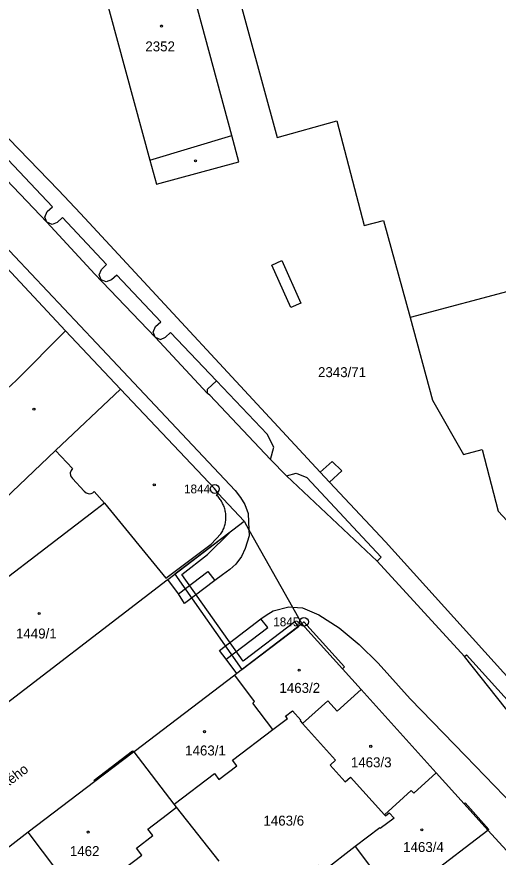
# Model space of a CAD drawing. Extents: x -821458 to -820266, y -1071458 to -1069826.
# Drawn here: x -821268.4 to -821186.2, y -1070550.7 to -1070407.2 of the extents above; entities that cross this region are included whole.
import ezdxf

# ---------------------------------------------------------------- set-up
doc = ezdxf.new("R2010")
doc.units = 0
for name, color, linetype in [('Vrstva 1', 7, 'Continuous'), ('Vrstva 13', 7, 'Continuous'), ('Vrstva 2', 7, 'Continuous'), ('Vrstva 4', 7, 'Continuous'), ('Vrstva 5', 7, 'Continuous'), ('Vrstva 7', 7, 'Continuous'), ('Vrstva 8', 7, 'Continuous')]:
    doc.layers.add(name, color=color, linetype=linetype)

msp = doc.modelspace()

# ---------------------------------------------------------------- linework, layer by layer
at = {"layer": 'Vrstva 1'}
for p, q in [((-821260.09, -1070460.79), (-821280.98, -1070438.5)), ((-821136.87, -1070441.33), (-821201.26, -1070458.54)), ((-821231.22, -1070519.61), (-821248.4, -1070532.7)), ((-821196.79, -1070536.31), (-821209.6, -1070522.1)), ((-821241.57, -1070541.65), (-821248.4, -1070532.7)), ((-821203.9, -1070558.21), (-821187.96, -1070546.11)), ((-821182.72, -1070551.87), (-821187.96, -1070546.11))]:
    msp.add_line(p, q, dxfattribs=at)
for points in [[(-821258.7, -1070367.71), (-821252.21, -1070365.96), (-821249.43, -1070365.21), (-821241.65, -1070362.96), (-821223.96, -1070427.77), (-821213.75, -1070424.96), (-821209.09, -1070442.84), (-821205.81, -1070441.98), (-821201.26, -1070458.54)], [(-821231.73, -1070427.45), (-821242.6, -1070387.17), (-821256.75, -1070390.96), (-821245.69, -1070431.69), (-821244.58, -1070435.78), (-821230.52, -1070431.97), (-821231.73, -1070427.45)], [(-821183.73, -1070520.92), (-821205.46, -1070496.83), (-821215, -1070486.68), (-821216.61, -1070484.97), (-821257.56, -1070440.79), (-821261.33, -1070436.77), (-821285.11, -1070412.22)], [(-821201.26, -1070458.54), (-821197.43, -1070472.66), (-821192.14, -1070481.93), (-821188.95, -1070481.1), (-821186.21, -1070491.62), (-821180.01, -1070498.29), (-821178.27, -1070497.75), (-821177.4, -1070501.1), (-821167.28, -1070512), (-821150.8, -1070507.61), (-821150.3, -1070509.44), (-821144.52, -1070507.96), (-821149.15, -1070489.84), (-821125.19, -1070483.48), (-821136.87, -1070441.33)], [(-821260.09, -1070460.79), (-821268.54, -1070469.28), (-821271.57, -1070472.02), (-821273.93, -1070474.15)], [(-821229.6, -1070493.33), (-821234.05, -1070488.58), (-821234.63, -1070487.82), (-821250.74, -1070470.77), (-821260.09, -1070460.79)], [(-821270.46, -1070489.5), (-821261.8, -1070481.24), (-821258.92, -1070484.33), (-821259.17, -1070484.65), (-821259.3, -1070485.04), (-821259.24, -1070485.58), (-821258.94, -1070486.03), (-821256.92, -1070488.18), (-821256.56, -1070488.5), (-821256.1, -1070488.63), (-821255.75, -1070488.6), (-821255.43, -1070488.46), (-821255.24, -1070488.28), (-821253.43, -1070490.23), (-821254.92, -1070491.37), (-821280.12, -1070510.63)], [(-821274.99, -1070528.04), (-821242.73, -1070503.37), (-821242.62, -1070503.28), (-821229.6, -1070493.33)], [(-821229.6, -1070493.33), (-821228.78, -1070494.79), (-821221.34, -1070508), (-821219.73, -1070510.86)], [(-821219.73, -1070510.86), (-821230.84, -1070519.32), (-821231.22, -1070519.61)], [(-821209.6, -1070522.1), (-821212.82, -1070518.52), (-821219.73, -1070510.86)], [(-821224.7, -1070528.92), (-821228.12, -1070524.38), (-821227.82, -1070524.15), (-821231.22, -1070519.61)], [(-821219.62, -1070527.87), (-821215.31, -1070524), (-821213.7, -1070525.78), (-821209.6, -1070522.1)], [(-821224.7, -1070528.92), (-821222.21, -1070527.03), (-821222.52, -1070526.64), (-821221.34, -1070525.7), (-821219.92, -1070527.32), (-821220.03, -1070527.42), (-821219.62, -1070527.87)], [(-821219.62, -1070527.87), (-821214, -1070534.15), (-821214.91, -1070535), (-821212.36, -1070537.82), (-821211.43, -1070537.02), (-821205.64, -1070543.47)], [(-821241.57, -1070541.65), (-821234.65, -1070536.44), (-821233.9, -1070537.43), (-821230.84, -1070535.14), (-821231.6, -1070534.16), (-821224.7, -1070528.92)], [(-821248.4, -1070532.7), (-821248.5, -1070532.78), (-821255.09, -1070537.77), (-821266.51, -1070546.45)], [(-821205.64, -1070543.47), (-821201.07, -1070539.3), (-821200.61, -1070539.8), (-821196.79, -1070536.31)], [(-821187.96, -1070546.11), (-821192.02, -1070541.61), (-821196.79, -1070536.31)], [(-821233.85, -1070551.4), (-821241.17, -1070542.18), (-821241.57, -1070541.65)], [(-821205.64, -1070543.47), (-821205.45, -1070543.68), (-821204.85, -1070543.14), (-821204, -1070544.07), (-821206.36, -1070545.8), (-821206.45, -1070545.69), (-821210.64, -1070548.9)], [(-821266.51, -1070546.45), (-821275.28, -1070553.19), (-821281.79, -1070558.19), (-821281.93, -1070558.3)], [(-821252.09, -1070565.54), (-821259.16, -1070556.17), (-821266.51, -1070546.45)], [(-821210.64, -1070548.9), (-821216.08, -1070553.08), (-821216.88, -1070552.13), (-821219.9, -1070554.44), (-821219.16, -1070555.43), (-821226.33, -1070561.12)], [(-821210.64, -1070548.9), (-821207.17, -1070553.5), (-821207.37, -1070553.65), (-821203.9, -1070558.21)]]:
    msp.add_lwpolyline(points, dxfattribs=at)
at = {"layer": 'Vrstva 13'}
msp.add_lwpolyline([(-821240.24, -1070502.41), (-821235.86, -1070499.01), (-821232.02, -1070495.18), (-821241.47, -1070502.4), (-821229.99, -1070518.67), (-821220.32, -1070511.31), (-821220.92, -1070510.51), (-821229.77, -1070517.25)], close=True, dxfattribs=at)
at = {"layer": 'Vrstva 4'}
for p, q in [((-821245.69, -1070431.69), (-821231.73, -1070427.45)), ((-821255.1, -1070451.15), (-821263.32, -1070442.26)), ((-821224.88, -1070449.57), (-821223.17, -1070448.82)), ((-821221.62, -1070456.84), (-821224.88, -1070449.57)), ((-821223.17, -1070448.82), (-821219.9, -1070456.06)), ((-821244.81, -1070461.92), (-821255.1, -1070451.15)), ((-821219.9, -1070456.06), (-821221.62, -1070456.84)), ((-821235.89, -1070471.54), (-821244.81, -1070461.92)), ((-821234.33, -1070469.35), (-821225.68, -1070478.48)), ((-821250.74, -1070470.77), (-821261.8, -1070481.24)), ((-821222.38, -1070485.56), (-821225.12, -1070482.77)), ((-821216.61, -1070484.97), (-821214.55, -1070483.11)), ((-821214.55, -1070483.11), (-821212.91, -1070484.72)), ((-821212.91, -1070484.72), (-821215, -1070486.68)), ((-821206.91, -1070500.17), (-821222.38, -1070485.56)), ((-821234.35, -1070488.84), (-821234.05, -1070488.58)), ((-821253.43, -1070490.23), (-821242.97, -1070503.05)), ((-821235.26, -1070497.23), (-821233.56, -1070495.47)), ((-821242.97, -1070503.05), (-821235.26, -1070497.23)), ((-821191.98, -1070516.44), (-821206.91, -1070500.17)), ((-821240.79, -1070505.74), (-821235.83, -1070501.94)), ((-821235.83, -1070501.94), (-821234.61, -1070503.48)), ((-821240.79, -1070505.74), (-821242.62, -1070503.28)), ((-821219.73, -1070510.86), (-821219.39, -1070510.52)), ((-821219.39, -1070510.52), (-821212.49, -1070518.23)), ((-821230.84, -1070519.32), (-821232.67, -1070516.9)), ((-821212.49, -1070518.23), (-821212.82, -1070518.52)), ((-821255.24, -1070537.57), (-821248.66, -1070532.57)), ((-821248.66, -1070532.57), (-821248.5, -1070532.78)), ((-821255.09, -1070537.77), (-821255.24, -1070537.57)), ((-821242.72, -1070543.38), (-821241.17, -1070542.18)), ((-821192.02, -1070541.61), (-821191.86, -1070541.46)), ((-821191.86, -1070541.46), (-821187.8, -1070545.96)), ((-821246.04, -1070545.94), (-821242.72, -1070543.38)), ((-821247.98, -1070549.17), (-821245.21, -1070547.02)), ((-821245.21, -1070547.02), (-821246.04, -1070545.94)), ((-821187.8, -1070545.96), (-821187.96, -1070546.11)), ((-821247.05, -1070550.38), (-821247.98, -1070549.17)), ((-821250.13, -1070552.73), (-821247.05, -1070550.38))]:
    msp.add_line(p, q, dxfattribs=at)
for points in [[(-821354.82, -1070356.72), (-821348.41, -1070363.52), (-821328.79, -1070384.4), (-821304.41, -1070410.3), (-821282.75, -1070433.29), (-821254.81, -1070462.93)], [(-821263.32, -1070442.26), (-821263.66, -1070441.37), (-821263.26, -1070440.44), (-821262.34, -1070439.62), (-821269.88, -1070431.62), (-821270.79, -1070432.49), (-821271.53, -1070432.83), (-821272.47, -1070432.49), (-821272.91, -1070431.35), (-821272.53, -1070430.62), (-821271.61, -1070429.79), (-821279.23, -1070421.71), (-821280.16, -1070422.54), (-821280.95, -1070422.88), (-821281.7, -1070422.85)], [(-821263.32, -1070442.26), (-821272.51, -1070432.62), (-821281.7, -1070422.85)], [(-821253.09, -1070449.47), (-821260.61, -1070441.46), (-821261.53, -1070442.28), (-821262.42, -1070442.63), (-821263.32, -1070442.26)], [(-821244.81, -1070461.92), (-821245.17, -1070461.02), (-821244.73, -1070460.06), (-821243.85, -1070459.29), (-821251.35, -1070451.3), (-821252.28, -1070452.12), (-821253.19, -1070452.47), (-821254.04, -1070452.08), (-821254.38, -1070451.27), (-821253.95, -1070450.31), (-821253.09, -1070449.47)], [(-821244.81, -1070461.92), (-821243.89, -1070462.31), (-821243.01, -1070461.92), (-821242.17, -1070461.09), (-821234.33, -1070469.35)], [(-821254.81, -1070462.93), (-821231.15, -1070488.06), (-821230.2, -1070489.29), (-821229.46, -1070490.47), (-821228.92, -1070491.99), (-821228.78, -1070494.79)], [(-821235.89, -1070471.54), (-821235.85, -1070470.75), (-821234.33, -1070469.35)], [(-821225.12, -1070482.77), (-821235.46, -1070471.81), (-821235.89, -1070471.54)], [(-821225.12, -1070482.77), (-821224.54, -1070480.67), (-821225.68, -1070478.48)], [(-821222.38, -1070485.56), (-821220.73, -1070485.12), (-821218.92, -1070485.86)], [(-821206.91, -1070500.17), (-821206.21, -1070499.47), (-821218.92, -1070485.86)], [(-821233.56, -1070495.47), (-821233.45, -1070495.3), (-821233.35, -1070495.12), (-821233.26, -1070494.95), (-821233.18, -1070494.76), (-821233.1, -1070494.58), (-821233.03, -1070494.39), (-821232.96, -1070494.2), (-821232.91, -1070494.01), (-821232.86, -1070493.81), (-821232.81, -1070493.61), (-821232.78, -1070493.42), (-821232.75, -1070493.22), (-821232.73, -1070493.02), (-821232.72, -1070492.82), (-821232.72, -1070492.61), (-821232.72, -1070492.41), (-821232.74, -1070492.21), (-821232.76, -1070492.01), (-821232.78, -1070491.81), (-821232.82, -1070491.61), (-821232.86, -1070491.42), (-821232.91, -1070491.22), (-821232.97, -1070491.03), (-821233.04, -1070490.84), (-821233.11, -1070490.65), (-821233.19, -1070490.47), (-821233.28, -1070490.29), (-821233.37, -1070490.11), (-821233.47, -1070489.93), (-821233.58, -1070489.76), (-821233.69, -1070489.6), (-821233.81, -1070489.44), (-821233.94, -1070489.28), (-821234.07, -1070489.13), (-821234.21, -1070488.98), (-821234.35, -1070488.84)], [(-821228.78, -1070494.79), (-821228.73, -1070495.81), (-821229.43, -1070498.01), (-821230.05, -1070499.36), (-821231.05, -1070500.67), (-821232.06, -1070501.56), (-821233.29, -1070502.47), (-821234.61, -1070503.48)], [(-821234.61, -1070503.48), (-821239.77, -1070507.39), (-821240.79, -1070505.74)], [(-821226.74, -1070509.98), (-821225.84, -1070509.35), (-821224.62, -1070508.64), (-821221.98, -1070507.95), (-821221.34, -1070508)], [(-821221.34, -1070508), (-821219.64, -1070508.14), (-821216.84, -1070509.33), (-821213.38, -1070511.56), (-821209.96, -1070514.37), (-821206.7, -1070517.55), (-821201.24, -1070523.68), (-821191.81, -1070533.38)], [(-821232.67, -1070516.9), (-821233.81, -1070515.41), (-821226.74, -1070509.98)], [(-821232.67, -1070516.9), (-821225.58, -1070511.46), (-821226.74, -1070509.98)], [(-821191.98, -1070516.44), (-821191.62, -1070516.15), (-821179.82, -1070529.19)], [(-821166.01, -1070547.63), (-821184.97, -1070525.27), (-821191.98, -1070516.44)], [(-821191.81, -1070533.38), (-821178.59, -1070547.05), (-821178.68, -1070547.3), (-821179.37, -1070549.25), (-821182.72, -1070551.87)]]:
    msp.add_lwpolyline(points, dxfattribs=at)
at = {"layer": 'Vrstva 5'}
for centre in [(-821243.73, -1070408.75), (-821237.93, -1070431.79), (-821265.5, -1070474.18), (-821244.95, -1070487.11), (-821264.61, -1070509.09), (-821220.2, -1070518.79), (-821236.36, -1070529.28), (-821207.99, -1070531.78), (-821256.23, -1070546.42), (-821199.25, -1070546.05)]:
    msp.add_circle(centre, 0.175, dxfattribs=at)
at = {"layer": 'Vrstva 8'}
for centre, radius in [((-821234.63, -1070487.82), 0.75), ((-821234.63, -1070487.82), 0.03), ((-821219.39, -1070510.52), 0.75), ((-821219.39, -1070510.52), 0.03)]:
    msp.add_circle(centre, radius, dxfattribs=at)

# ---------------------------------------------------------------- texts
at = {"layer": 'Vrstva 2'}
for s, p in [('2352', (-821246.48, -1070413.08)), ('2343/71', (-821216.99, -1070468.72)), ('1449/1', (-821268.57, -1070513.36)), ('1463/2', (-821223.58, -1070522.65)), ('1463/1', (-821239.68, -1070533.34)), ('1463/3', (-821211.38, -1070535.36)), ('1463/6', (-821226.31, -1070545.32)), ('1463/4', (-821202.45, -1070549.83)), ('1462', (-821259.37, -1070550.53))]:
    msp.add_text(s, height=1.7, dxfattribs=at).set_placement(p)
at = {"layer": 'Vrstva 7'}
msp.add_text('Sladkovského', height=1.7, rotation=37, dxfattribs=at).set_placement((-821277.6, -1070544.54))
at = {"layer": 'Vrstva 8'}
for s, p in [('1844', (-821239.88, -1070488.57)), ('1845', (-821224.64, -1070511.27))]:
    msp.add_text(s, height=1.5, dxfattribs=at).set_placement(p)

doc.saveas('drawing.dxf')
